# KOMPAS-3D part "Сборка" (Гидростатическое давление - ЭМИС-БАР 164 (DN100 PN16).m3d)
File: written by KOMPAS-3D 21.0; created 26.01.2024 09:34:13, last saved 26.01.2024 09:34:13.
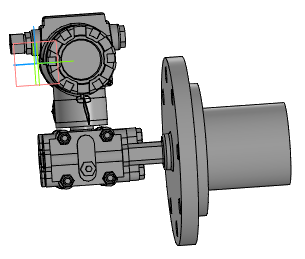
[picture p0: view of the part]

Document properties: Автор: Admin; Организация: office.local; Полное имя файла: S:\Эмис\Инженерный\Расходомеры и фильтры\Задачи\Черненков А.А\ЭМИС-БАР\3D-модели для сайта\Датчики гидростатического давления ЭМИС-БАР\Компоненты\ЭМИС-БАР 164.m3d

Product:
- Part/product: Сборка
    Масса: 21.037743

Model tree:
1. Операция без истории:1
